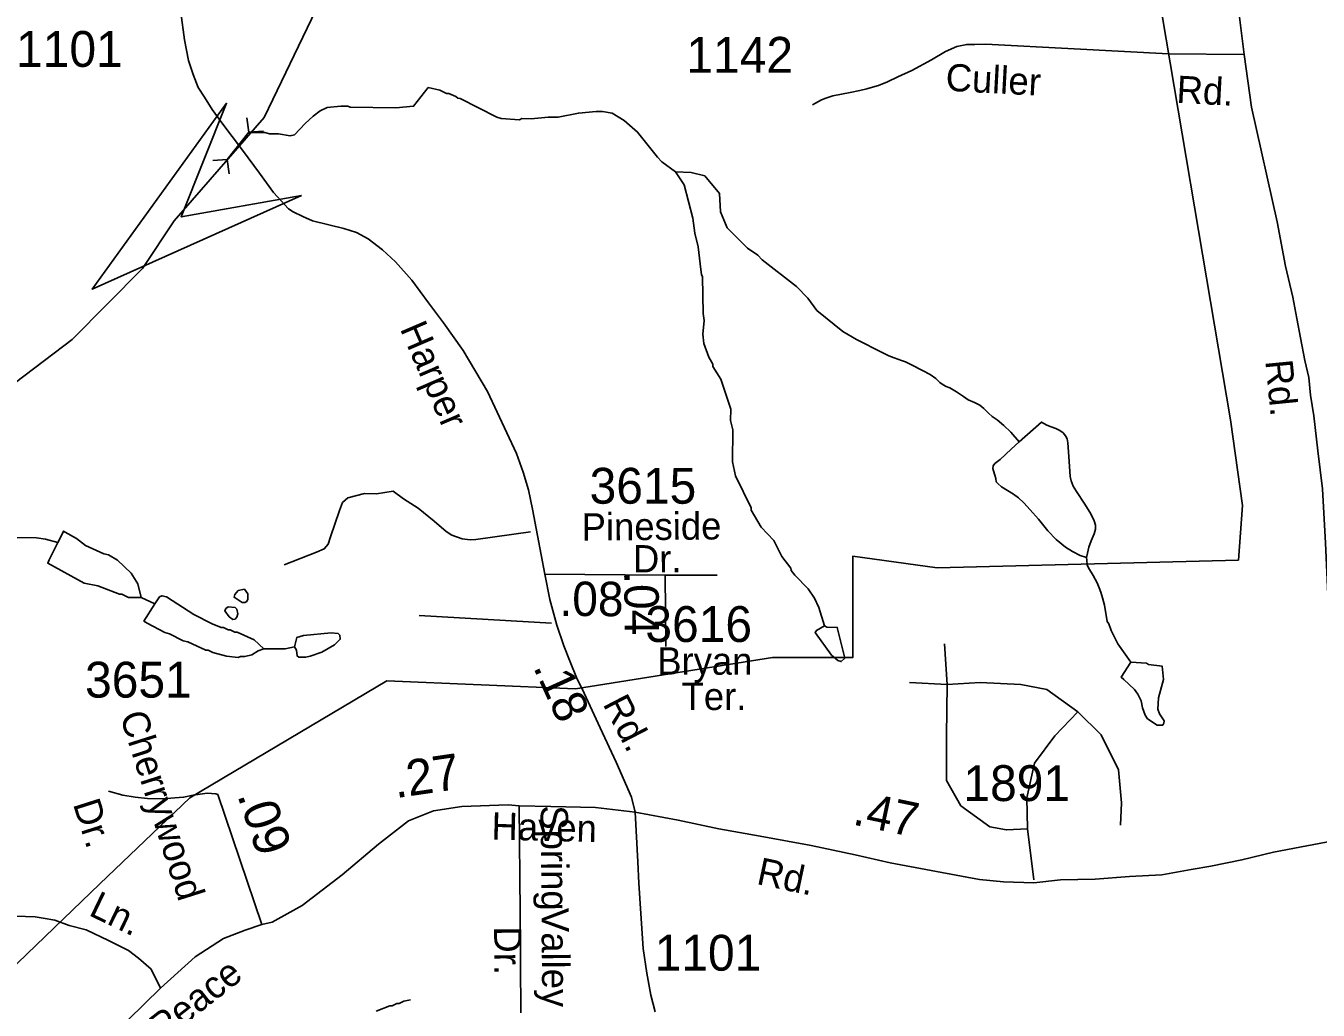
# Model space of a CAD drawing. Extents: x 1547597 to 1699558, y 810033 to 920809.
# Drawn here: x 1585386 to 1589892, y 836281 to 839713 of the extents above; entities that cross this region are included whole.
import ezdxf

# ---------------------------------------------------------------- set-up
doc = ezdxf.new("R2010")
doc.units = 0
for name, color, linetype in [('Exist Boundary Political City Limit New', 7, 'Continuous'), ('Exist Hydrographic Creek Single Shore', 7, 'Continuous'), ('Exist Hydrographic Misc Water Feature', 7, 'Continuous'), ('Exist Road Non-System Type 51', 7, 'Continuous'), ('Exist Road Non-System Type 51 Label', 7, 'Continuous'), ('Exist Road Secondary Mileage Hundredths English Label', 7, 'Continuous'), ('Exist Road Secondary Structure Culvert Attributed CELL', 7, 'Continuous'), ('Exist Road Secondary Structure Culvert CELL', 7, 'Continuous'), ('Exist Road Secondary Type 41 Attributed', 7, 'Continuous'), ('Exist Road Secondary Type 51 Attributed', 7, 'Continuous'), ('Exist Road Secondary Type 51 Label', 7, 'Continuous'), ('Exist Road Secondary Type 51 Number Label', 7, 'Continuous'), ('Map Preparation Boundary City Limit Buffer Line', 7, 'Continuous')]:
    doc.layers.add(name, color=color, linetype=linetype)

msp = doc.modelspace()

# ---------------------------------------------------------------- linework, layer by layer
at = {"layer": 'Exist Boundary Political City Limit New'}
msp.add_lwpolyline([(1589306.2, 839997.4), (1589586.4, 838339.2), (1589628.4, 838040.1), (1589614.4, 837849.8), (1588563.9, 837822.7), (1588269.7, 837863.4), (1588269.7, 837510), (1587989.5, 837510), (1587303.2, 837401.3), (1586644.8, 837428.5), (1585958.5, 837020.7), (1585644.7, 836721.7), (1585229.2, 836322.9)], dxfattribs=at)
at = {"layer": 'Exist Hydrographic Creek Single Shore'}
msp.add_lwpolyline([(1585117.5, 838293.2), (1585547.6, 838619.3), (1585792.5, 838867), (1585903.6, 839032.3), (1586217.5, 839393.6), (1586397.5, 839767.4), (1586761.5, 840718.6), (1586859.5, 841126.9), (1586879.5, 841970.2), (1586957.5, 842238.7), (1586986.8, 842579.1), (1586985.5, 842926.6), (1587021.2, 843660.8), (1587109.6, 843958.2), (1587214.6, 844349.9), (1587369.6, 844655.4), (1587407.5, 844969.8), (1587404.6, 845370.3), (1587343.5, 845755.6), (1587421.6, 845980.6), (1587450.6, 846262.3), (1587508.6, 847345.1)], dxfattribs=at)
at = {"layer": 'Exist Hydrographic Misc Water Feature'}
msp.add_line((1585835.8, 837697.6), (1585788.9, 837719.8), dxfattribs=at)
for points in [[(1587650.9, 839203.7), (1587604.3, 839239.1), (1587588.5, 839255.3), (1587519.5, 839342.1), (1587472, 839382.7), (1587430.2, 839408.5), (1587397.5, 839414), (1587374.7, 839414.3), (1587312.9, 839408.7), (1587242.2, 839394.5), (1587207.9, 839394.2), (1587148.1, 839388.8), (1587116.1, 839389.2), (1587108.1, 839385.3), (1587044.2, 839390.1), (1587028.3, 839394.3), (1586901, 839459.9), (1586893, 839460), (1586885.2, 839466.1), (1586861.3, 839476.4), (1586853.3, 839476.5), (1586829.4, 839488.7), (1586789.5, 839497.2), (1586738.4, 839432.6), (1586676.7, 839426.7), (1586516.8, 839428.7), (1586508.8, 839432.8), (1586484.8, 839433.1), (1586436.8, 839427.7), (1586412.6, 839416), (1586388.4, 839398.3), (1586360.1, 839372.7), (1586323.6, 839333.2), (1586307.6, 839329.4), (1586267.7, 839335.8), (1586235.8, 839336.3), (1586219.8, 839340.5), (1586162.6, 839341.2)], [(1588282.8, 838618.8), (1588235.1, 838647.4), (1588144, 838720.5), (1588112.5, 838762.9), (1588073, 838803.4), (1587954.1, 838896.8), (1587938.3, 838913), (1587902.6, 838937.5), (1587831.5, 839008.3), (1587808.2, 839064.6), (1587804.9, 839128.6), (1587753.7, 839189.2), (1587705.8, 839201.8), (1587650.9, 839203.7)], [(1588170.9, 837620.7), (1588151.7, 837684.9), (1588136.1, 837717.1), (1588114.4, 837749.4), (1588067.1, 837797.9), (1588055.3, 837814.1), (1588053.3, 837822.1), (1588021.9, 837862.4), (1587994.5, 837918.8), (1587949.6, 837964.4), (1587915.7, 838023.7), (1587915.8, 838031.7), (1587861.2, 838144.3), (1587849.8, 838192.5), (1587851.2, 838304.4), (1587843.5, 838336.5), (1587844, 838376.5), (1587809.2, 838480.9), (1587781.7, 838525.2), (1587781.8, 838533.2), (1587768.1, 838557.4), (1587750.7, 838605.6), (1587747.1, 838637.6), (1587751.7, 838685.5), (1587747.9, 838709.5), (1587745.5, 838837.5), (1587741.6, 838845.6), (1587739.8, 838863.6), (1587730.1, 838942.3), (1587719.3, 838989.8), (1587711.9, 839041.9), (1587681.3, 839158.2), (1587650.9, 839203.7)], [(1588849.8, 838262.8), (1588820.9, 838295.6), (1588795.7, 838319.6), (1588772.6, 838338.5), (1588755.6, 838350.3), (1588743, 838361.9), (1588726.2, 838378.6), (1588712.8, 838390.3), (1588694.4, 838399.1), (1588671.8, 838408.8), (1588655.6, 838419.8), (1588631, 838436.6), (1588607.7, 838450.6), (1588595.6, 838455), (1588585, 838460.9), (1588573, 838469.7), (1588559, 838482.8), (1588539.3, 838497.4), (1588513.2, 838511.4), (1588474.3, 838530.7), (1588453.1, 838541.7), (1588438.9, 838545.6), (1588413.4, 838555.3), (1588395.1, 838562), (1588374.6, 838572.4), (1588282.8, 838618.8)], [(1588849.8, 838262.8), (1588928.1, 838331.1), (1588946.2, 838320.6), (1588961, 838314.2), (1588977.2, 838309.2), (1588992, 838302.2), (1589003.3, 838293.2), (1589011.2, 838282.9), (1589016.5, 838272.6), (1589019.6, 838258.3), (1589022.9, 838211.5), (1589027.1, 838141.1), (1589030.9, 838126.1), (1589038, 838107.6), (1589049.3, 838089.2), (1589078.3, 838045.3), (1589099.4, 838011.7), (1589111.2, 837987.2), (1589115.6, 837972.1), (1589115.4, 837957.3), (1589111, 837941.1), (1589100.4, 837916.9), (1589092.6, 837894.7), (1589087.5, 837873.8), (1589084.5, 837859.6)], [(1589084.5, 837859.6), (1589062.3, 837866.1), (1589036.2, 837879.5), (1589011.3, 837895.5), (1588978.6, 837921.8), (1588950, 837952.2), (1588916.9, 837992.7), (1588887.6, 838025.7), (1588866.4, 838049.8), (1588847, 838067.1), (1588830.3, 838080.3), (1588808.9, 838092.2), (1588788, 838105.4), (1588775.4, 838116.5), (1588770.1, 838123.3), (1588768.3, 838134.2), (1588765.1, 838146.4), (1588759.9, 838160.7), (1588757.4, 838169.6), (1588758.9, 838179), (1588765.1, 838186.4), (1588782.9, 838201), (1588822.2, 838236.2), (1588849.8, 838262.8)], [(1585498, 837911.5), (1585455.1, 837922.7), (1585423.1, 837927.1), (1585263.2, 837929.1), (1585255.2, 837925.2), (1585223.2, 837923.7), (1585201.1, 837909.9), (1585184.9, 837894.1), (1585142, 837822.7), (1585131.8, 837798.8), (1585076.6, 837703.6), (1585043.9, 837640), (1584982.7, 837536.8), (1584900.8, 837378), (1584823.2, 837243), (1584756, 837139.8), (1584711, 837060.5), (1584688.8, 837042.8), (1584632.7, 837025.5), (1584624.7, 837025.6), (1584608.6, 837017.8), (1584544.4, 837002.6), (1584496.4, 836999.2), (1584442.4, 836986.5)], [(1585788.9, 837719.8), (1585744.7, 837719.2), (1585720.8, 837731.5), (1585712.8, 837731.6), (1585637.1, 837760.5), (1585589.2, 837769.1), (1585462.8, 837838.8), (1585468.2, 837850.6), (1585498, 837911.5)], [(1585498, 837911.5), (1585511.3, 837938), (1585517.8, 837951), (1585523.4, 837947.9), (1585563.1, 837925.3), (1585594.9, 837901), (1585658.4, 837872.2), (1585674.4, 837868), (1585706.2, 837849.6), (1585753.7, 837805), (1585777.2, 837766.7), (1585788.9, 837719.8)], [(1589147.6, 837692.4), (1589140.4, 837718.9), (1589135, 837738.4), (1589129.1, 837753.7), (1589121.1, 837770.7), (1589107.9, 837796.2), (1589091.1, 837822.8), (1589086.6, 837833.3), (1589085.1, 837849.5), (1589084.5, 837859.6)], [(1586148.8, 837748.7), (1586160.7, 837731.9), (1586160.5, 837713.9), (1586156.4, 837706), (1586150.4, 837702.1), (1586140.3, 837702.2), (1586112.5, 837720.6), (1586114.7, 837730.5), (1586126.9, 837744.3), (1586148.8, 837748.7)], [(1585835.8, 837697.6), (1585798, 837637.1), (1585809.6, 837630.4), (1585871.2, 837597.6), (1585887.1, 837593.4), (1585934.8, 837568.9), (1585950.7, 837564.7), (1586014.4, 837535.8), (1586022.4, 837535.7), (1586038.3, 837527.5), (1586086.2, 837515), (1586126.1, 837510.5), (1586134.2, 837514.4), (1586150.1, 837514.2), (1586174.1, 837519.9), (1586196.3, 837533.6), (1586215.6, 837540.8)], [(1586215.6, 837540.8), (1586182.7, 837571.7), (1586123.1, 837598.5), (1586115.1, 837598.5), (1586099.2, 837606.7), (1586091.2, 837606.8), (1586075.3, 837615.1), (1586067.3, 837615.2), (1586035.5, 837627.6), (1585971.9, 837660.4), (1585876.6, 837721.5), (1585860.7, 837725.7), (1585852.6, 837721.8), (1585835.8, 837697.6)], [(1586116.1, 837684.5), (1586092.2, 837686.8), (1586084.1, 837680.9), (1586080, 837673), (1586094.7, 837652.3), (1586107.6, 837642.6), (1586115.7, 837644.5), (1586121.7, 837650.5), (1586125.8, 837662.4), (1586122.1, 837678.5), (1586116.1, 837684.5)], [(1589239.6, 837493.6), (1589193.9, 837557.9), (1589170.6, 837604.1), (1589162.8, 837628.2), (1589156.9, 837636.3), (1589147.6, 837692.4)], [(1586322.5, 837548), (1586330.9, 837579.9), (1586354.9, 837587.6), (1586451.1, 837596.3), (1586474.9, 837594), (1586480.9, 837588), (1586482.7, 837573.9), (1586462.5, 837554.2), (1586418.3, 837528.8), (1586378.1, 837515.3), (1586362.1, 837511.5), (1586338.1, 837511.8), (1586332.1, 837515.9), (1586330.3, 837535.9), (1586322.5, 837548)], [(1588170.9, 837620.7), (1588178.9, 837616.6), (1588215.5, 837615.4), (1588241.6, 837507.9), (1588229.5, 837496), (1588217.5, 837500.2), (1588195.7, 837518.4), (1588138.6, 837597.1), (1588142.7, 837605.1), (1588170.9, 837620.7)], [(1586322.5, 837548), (1586290.4, 837540.4), (1586215.6, 837540.8)], [(1589239.6, 837493.6), (1589293.2, 837490.6), (1589301.1, 837486.5), (1589348.4, 837480), (1589352.4, 837433.9), (1589335.7, 837370.2), (1589333.3, 837330.2), (1589339, 837314.1), (1589354.8, 837290), (1589354.7, 837282), (1589350.6, 837274), (1589330.6, 837274.3), (1589296.9, 837296.7), (1589289, 837308.8), (1589279.3, 837334.9), (1589275.5, 837358.9), (1589263.9, 837383.1), (1589252.1, 837399.2), (1589214.4, 837433.7), (1589204.9, 837442.4), (1589239.6, 837493.6)], [(1586727.8, 836317.4), (1586703.7, 836311.7), (1586687.6, 836303.9), (1586679.6, 836304.1), (1586663.6, 836296.3), (1586655.6, 836296.4), (1586607.3, 836277)]]:
    msp.add_lwpolyline(points, dxfattribs=at)
at = {"layer": 'Exist Road Non-System Type 51'}
for p, q in [((1587615.9, 837796.9), (1587796.4, 837796.9)), ((1587219.1, 837630.6), (1586757.2, 837656.8))]:
    msp.add_line(p, q, dxfattribs=at)
for points in [[(1588318, 839493.5), (1588294.5, 839487.3), (1588260.3, 839479.8), (1588230.2, 839474.4), (1588200.1, 839468.8), (1588175.9, 839461.1), (1588160, 839455.2), (1588129.6, 839437.8)], [(1587146.2, 837948.6), (1586955.1, 837922.1), (1586935.2, 837920.3), (1586907.1, 837924.7), (1586871.3, 837937.2), (1586851.6, 837949.4), (1586810.1, 837986.1), (1586754.6, 838031.1), (1586703, 838063.7), (1586667.5, 838090.2), (1586609.3, 838081.2), (1586567.3, 838081.7), (1586509.1, 838066.6), (1586490.8, 838050.8), (1586480.4, 838023), (1586449, 837931.4), (1586440.6, 837905.5), (1586426.5, 837889.6), (1586400.3, 837878.1), (1586287.5, 837833.6)], [(1588589.1, 837557.7), (1588599.2, 837415.9)], [(1588599.2, 837415.9), (1588467.6, 837422.7)], [(1588599.2, 837415.9), (1588595.8, 837237), (1588595.8, 837081.6), (1588646.4, 836993.8), (1588747.7, 836919.5), (1588805, 836909.4), (1588879.2, 836912.8)], [(1589054.7, 837321.4), (1588946.7, 837399), (1588855.6, 837415.9), (1588713.9, 837422.7), (1588599.2, 837415.9)], [(1588879.2, 836912.8), (1588875.9, 837020.8), (1588902.9, 837142.4), (1588973.7, 837237), (1589054.7, 837321.4)], [(1589054.7, 837321.4), (1589135.6, 837240.3), (1589196.4, 837118.8), (1589206.5, 837004), (1589203.1, 836926.3)], [(1586056, 837032.6), (1586048.4, 837035.4), (1586018.4, 837037.8), (1585970.2, 837030.6), (1585936.1, 837023), (1585861.9, 837018.1), (1585810.1, 837018.8), (1585768, 837023.4), (1585724.1, 837030.1), (1585674.4, 837044.8)], [(1587106.3, 836993.4), (1587109.8, 836621.4), (1587112.6, 836271.9)], [(1588879.2, 836912.8), (1588900.7, 836735.5)], [(1585855.8, 836357), (1585822.9, 836423.8), (1585779.4, 836462.3), (1585743.8, 836488.8), (1585674.2, 836523.9), (1585596.7, 836561.1), (1585537, 836575.9), (1585487.2, 836594.7), (1585447.3, 836601.3), (1585419.3, 836605.7), (1585351.4, 836608.6), (1584939.2, 836612.6)]]:
    msp.add_lwpolyline(points, dxfattribs=at)
at = {"layer": 'Exist Road Secondary Structure Culvert Attributed CELL'}
msp.add_lwpolyline([(1586348, 839121.6), (1585618.1, 838794.1), (1586086.5, 839442.6), (1585928.2, 839046.7)], close=True, dxfattribs=at)
at = {"layer": 'Exist Road Secondary Structure Culvert CELL'}
for p, q in [((1586157.2, 839391.9), (1586164.2, 839341.6)), ((1586088.7, 839247.1), (1586164.2, 839341.6)), ((1586214.8, 839345.8), (1586164.2, 839341.6)), ((1586038.1, 839242.9), (1586088.7, 839247.1)), ((1586095.7, 839196.8), (1586088.7, 839247.1))]:
    msp.add_line(p, q, dxfattribs=at)
at = {"layer": 'Exist Road Secondary Type 41 Attributed'}
msp.add_lwpolyline([(1589041.2, 839632.6), (1588733, 839649.1), (1588695, 839647.7), (1588667, 839648.1), (1588632.8, 839640.5), (1588592.6, 839623.1), (1588544, 839593.7), (1588475.6, 839556.9), (1588427.2, 839535.4), (1588391, 839518), (1588358.7, 839504.4), (1588330.5, 839496.8), (1588318, 839493.5)], dxfattribs=at)
at = {"layer": 'Exist Road Secondary Type 51 Attributed'}
for points in [[(1589634.3, 839612.3), (1589602.1, 839874.3), (1589564.2, 840397.5), (1589477.6, 841011.9)], [(1585926.5, 839759.3), (1585939.5, 839663.8), (1585953.7, 839592.4), (1585969.9, 839543.5), (1585987.6, 839498.1), (1586008.8, 839463.9), (1586035.9, 839421.4), (1586070.1, 839374.2), (1586141.2, 839279.3), (1586201.4, 839198.5), (1586250.3, 839131.8), (1586302.1, 839074.5), (1586318.1, 839064), (1586351.8, 839048.1), (1586386, 839033.4), (1586494.8, 839005.6), (1586539.6, 838992.1), (1586580.3, 838969.7), (1586630.1, 838931.3), (1586675.5, 838889.5), (1586732.1, 838826.3), (1586790.5, 838746.7), (1586842.4, 838677.1), (1586910.6, 838581), (1586996.5, 838437.6), (1587096.9, 838221.8), (1587120.8, 838157), (1587139.1, 838095), (1587152.9, 838027.2), (1587170.6, 837935.2), (1587196.3, 837801.3)], [(1589634.3, 839612.3), (1589370.8, 839615), (1589041.2, 839632.6)], [(1589968.8, 836875.5), (1589959, 837014), (1589949.3, 837125.1), (1589945.4, 837246), (1589937.6, 837386.3), (1589939.6, 837520.9), (1589926.7, 837705.6), (1589917.9, 837909.1), (1589907.4, 838098.3), (1589891.5, 838230.9), (1589877.4, 838352.5), (1589865.7, 838424.6), (1589859.8, 838487), (1589846.2, 838545.5), (1589830.6, 838625.4), (1589817.3, 838692.6), (1589803.4, 838766.9), (1589778, 838875), (1589748.8, 839029), (1589659.4, 839429.4), (1589634.3, 839612.3)], [(1587196.3, 837801.3), (1587615.9, 837796.9)], [(1587196.3, 837801.3), (1587212.8, 837712.3), (1587237.9, 837623.2), (1587262.6, 837550.7), (1587284.2, 837495.8), (1587306.6, 837440.4), (1587332.5, 837385.6), (1587389.1, 837265.3), (1587444.6, 837144.9), (1587498.2, 837024), (1587511.2, 836971.5)], [(1587615.9, 837796.9), (1587618.2, 837548.2)], [(1586208.7, 836579.8), (1586056, 837032.6)], [(1586208.7, 836579.8), (1586245.3, 836587.2), (1586349.7, 836645.2), (1586488.8, 836752.5), (1586616.4, 836859.9), (1586720.7, 836941.1), (1586807.7, 836975.9), (1586906.3, 836990.5), (1587068.6, 836996.3), (1587106.3, 836993.4), (1587216.4, 836990.5), (1587373, 836987.6), (1587511.2, 836971.5)], [(1587511.2, 836971.5), (1587660.4, 836943.8), (1587802.9, 836913.2), (1587946.7, 836887.3), (1588124.3, 836854.7), (1588277.7, 836822.3), (1588399.7, 836794.6), (1588667, 836744.6), (1588711.7, 836736.8), (1588794.7, 836728.8), (1588900.4, 836725), (1588993.5, 836735.5), (1589115.1, 836738), (1589234.2, 836747.4), (1589347.3, 836752.9), (1589449.6, 836771.4), (1589517.8, 836782.4), (1589626.2, 836804.8), (1589736.2, 836831.4), (1589968.8, 836875.5)], [(1587511.2, 836971.5), (1587520.7, 836798.2), (1587523.9, 836723.3), (1587530.4, 836617.7), (1587538.6, 836496.2), (1587551.6, 836410.1), (1587565.2, 836332.8), (1587580.1, 836274.8)], [(1585742.8, 836246.8), (1585855.8, 836357), (1585976.8, 836466.9), (1586075.4, 836530.7), (1586150.7, 836559.7), (1586208.7, 836579.8)]]:
    msp.add_lwpolyline(points, dxfattribs=at)
at = {"layer": 'Map Preparation Boundary City Limit Buffer Line'}
msp.add_lwpolyline([(1589306.2, 839997.4), (1589586.4, 838339.2), (1589628.4, 838040.1), (1589614.4, 837849.8), (1588563.9, 837822.7), (1588269.7, 837863.4), (1588269.7, 837510), (1587989.5, 837510), (1587303.2, 837401.3), (1586644.8, 837428.5), (1585958.5, 837020.7), (1585644.7, 836721.7), (1585229.2, 836322.9)], dxfattribs=at)

# ---------------------------------------------------------------- texts
at = {"layer": 'Exist Road Non-System Type 51 Label'}
for s, rotation, p in [('Spring', 270.4666, (1587181.2, 836994.7)), ('Ln.', 334.3601, (1585601.9, 836613.3)), ('Valley', 270.4666, (1587184, 836636.9)), ('Dr.', 270.4666, (1587018.8, 836572.5))]:
    msp.add_text(s, height=95, rotation=rotation, dxfattribs=at).set_placement(p)
at = {"layer": 'Exist Road Secondary Mileage Hundredths English Label'}
for s, height, rotation, p in [('.08', 120, 359.6933, (1587246.8, 837655.4)), ('.04', 120, 270.5401, (1587472.3, 837810.6)), ('.18', 120, 294.4601, (1587153.9, 837477.4)), ('.27', 125, 8.3732, (1586676, 837019.7)), ('.09', 125, 288.6413, (1586122.7, 837030.5)), ('.47', 120, 348.1307, (1588265.8, 836928.9))]:
    msp.add_text(s, height=height, rotation=rotation, dxfattribs=at).set_placement(p)
at = {"layer": 'Exist Road Secondary Type 51 Label'}
for s, rotation, p in [('Culler', 356.9385, (1588591.7, 839486.6)), ('Rd.', 356.9385, (1589396.7, 839444.5)), ('Harper', 293.29, (1586689.5, 838657)), ('Rd.', 275.6534, (1589707.8, 838544.6)), ('Pineside', 0.5186, (1587324.6, 837917.8)), ('Dr.', 0.0595, (1587503.3, 837807.1)), ('Bryan', 359.824, (1587587.7, 837451)), ('Ter.', 359.9786, (1587672.7, 837327.3)), ('Rd.', 297.3847, (1587396.3, 837348.8)), ('Cherrywood', 287.6208, (1585713.3, 837307.8)), ('Dr.', 287.6208, (1585549.9, 837000)), ('Haven', 358.5494, (1587009, 836875.8)), ('Rd.', 348.0731, (1587930.7, 836721.2)), ('Peace', 38.2582, (1585865.7, 836170.6))]:
    msp.add_text(s, height=95, rotation=rotation, dxfattribs=at).set_placement(p)
at = {"layer": 'Exist Road Secondary Type 51 Number Label'}
for s, p in [('1101', (1585352.4, 839569.6)), ('1142', (1587689.5, 839549.1)), ('3615', (1587352, 838046.6)), ('3616', (1587546.5, 837564.5)), ('3651', (1585592.8, 837370.6)), ('1891', (1588655.4, 837009.9)), ('1101', (1587578.7, 836418.5))]:
    msp.add_text(s, height=125, dxfattribs=at).set_placement(p)

doc.saveas('drawing.dxf')
